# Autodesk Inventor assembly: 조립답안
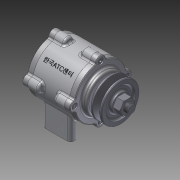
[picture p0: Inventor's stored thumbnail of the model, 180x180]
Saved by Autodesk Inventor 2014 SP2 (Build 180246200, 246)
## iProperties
Created: 2015-03
Part Number: 조립답안
Document SubType Name: Assembly
Designer: 201-11
Author: 201-11
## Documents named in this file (11)
- C:\Users\201-11\Desktop\450305V1021\답안조립품.iam
- C:\Users\201-11\Desktop\450305V1021\1-본체.ipt
- C:\Users\201-11\Desktop\450305V1021\축.ipt
- C:\Users\201-11\Desktop\450305V1021\V벨트풀리.ipt
- C:\Users\201-11\Desktop\450305V1021\커버.ipt
- C:\Users\201-11\Desktop\450305V1021\커버2.ipt
- C:\Users\201-11\Desktop\450305V1021\베어링 6204.ipt
- C:\Users\201-11\Desktop\450305V1021\오일실.ipt
- C:\Users\201-11\Desktop\450305V1021\키(4 x 4 x 12).ipt
- C:\Users\201-11\Desktop\450305V1021\너트 M12x1.25.ipt
- C:\Users\201-11\Desktop\450305V1021\M 4 x 12.ipt
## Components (15 placed, 7 different names)
1. 1-본체:1 — 각도:1
2. 그루브 풀리1:1 — 각도:1
3. KS B 2023 6204 - 20 x 47 x 14:1
4. KS B 2023 6204 - 20 x 47 x 14:2
5. KS B 2804 D D - 20 32 8:1
6. KS B 1311 (I) 4 x 4 x 12:1
7. KS B 1012 클래스 1 일반 - 미터 M12x1.25:1
8. KS B 1003 - 미터 M 4 x 12:2
9. KS B 1003 - 미터 M 4 x 12:3
10. KS B 1003 - 미터 M 4 x 12:4
11. KS B 1003 - 미터 M 4 x 12:5
12. KS B 1003 - 미터 M 4 x 12:1
13. KS B 1003 - 미터 M 4 x 12:6
14. KS B 1003 - 미터 M 4 x 12:7
15. KS B 1003 - 미터 M 4 x 12:8
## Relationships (1: Angle 1)
- 각도:1 [Angle]: 1-본체:1 ↔ 그루브 풀리1:1
